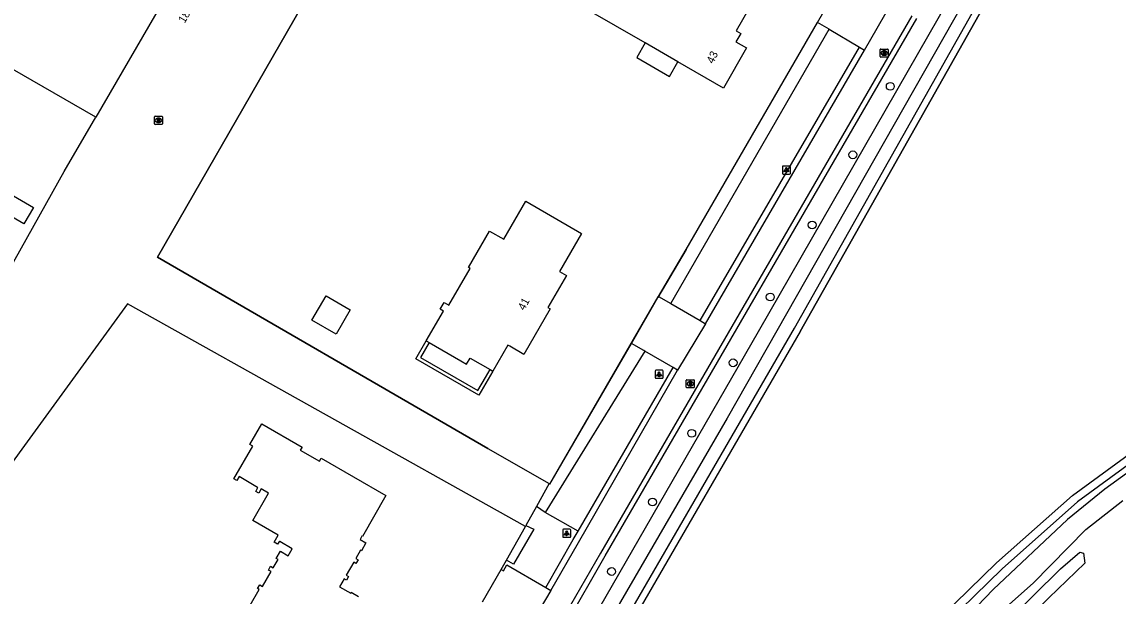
# Model space of a CAD drawing. Extents: x 156502 to 159074, y 384229 to 386094.
# Drawn here: x 157237.7 to 157374.7, y 385716.9 to 385788.7 of the extents above; entities that cross this region are included whole.
import ezdxf

# ---------------------------------------------------------------- set-up
doc = ezdxf.new("R2010")
doc.units = 0
for name, color, linetype in [('IMGEO_Boom', 7, 'Continuous'), ('IMGEO_Gemengd_bos', 7, 'Continuous'), ('IMGEO_Grasland_overig', 7, 'Continuous'), ('IMGEO_Greppel_droge_sloot', 7, 'Continuous'), ('IMGEO_Groenvoorziening', 7, 'Continuous'), ('IMGEO_Hek', 7, 'Continuous'), ('IMGEO_Lichtpunt', 7, 'Continuous'), ('IMGEO_Muur', 7, 'Continuous'), ('IMGEO_Pand', 7, 'Continuous'), ('IMGEO_Pand_nummerreeks', 7, 'Continuous'), ('IMGEO_Pand_overbouw', 7, 'Continuous'), ('IMGEO_Rijbaan_lokaal_halfverhard', 7, 'Continuous'), ('IMGEO_Rijbaan_lokaal_onverhard', 7, 'Continuous'), ('IMGEO_Rijbaan_lokaal_open', 7, 'Continuous'), ('IMGEO_Rioolput', 7, 'Continuous'), ('IMGEO_Waterloop', 7, 'Continuous')]:
    doc.layers.add(name, color=color, linetype=linetype)

msp = doc.modelspace()

# ---------------------------------------------------------------- linework, layer by layer
at = {"layer": 'IMGEO_Boom'}
for centre in [(157346.21, 385780.62), (157341.53, 385772.07), (157336.45, 385763.3), (157331.21, 385754.3), (157326.57, 385746.07), (157321.4, 385737.26), (157316.5, 385728.67), (157311.38, 385719.98)]:
    msp.add_circle(centre, 0.489, dxfattribs=at)
at = {"layer": 'IMGEO_Gemengd_bos'}
for points in [[(157395.47, 385857.33), (157372.59, 385816.74), (157334.96, 385750), (157287.88, 385668.68), (157271.39, 385640.19), (157191.03, 385500), (157152.55, 385432.88), (157150.67, 385429.59), (157146.17, 385421.74)], [(157272.04, 385820.04), (157246.93, 385776.79)], [(157272.04, 385820.04), (157275.52, 385818.05), (157285.22, 385812.46), (157254.63, 385759.26), (157295.91, 385735.36), (157303.57, 385730.97)], [(157300.61, 385725.63), (157250.89, 385753.43), (157232.44, 385728.12), (157222.97, 385734.27), (157242.96, 385769.96), (157246.93, 385776.79)], [(157303.57, 385730.97), (157301.99, 385728.11)], [(157301.99, 385728.11), (157300.68, 385725.75)], [(157300.61, 385725.63), (157300.68, 385725.75)]]:
    msp.add_lwpolyline(points, dxfattribs=at)
at = {"layer": 'IMGEO_Grasland_overig'}
msp.add_lwpolyline([(157246.93, 385776.79), (157216.71, 385794.2)], dxfattribs=at)
at = {"layer": 'IMGEO_Greppel_droge_sloot'}
for points in [[(157393.36, 385858.05), (157393.11, 385857.61), (157362.75, 385804.11), (157325.82, 385739.17), (157293.92, 385684.22), (157277.51, 385655.56), (157259.26, 385623.71), (157238.62, 385587.75), (157224.85, 385563.79), (157203.07, 385525.9), (157174.27, 385475.36), (157161.25, 385452.05), (157151.08, 385433.93), (157146.7, 385427.27), (157144.86, 385424.97)], [(157146.46, 385424.36), (157148.98, 385428.05), (157150.58, 385430.99), (157151.89, 385433.4), (157190.31, 385500.41), (157270.67, 385640.6), (157287.16, 385669.09), (157334.24, 385750.41), (157371.86, 385817.15), (157394.6, 385857.47)]]:
    msp.add_lwpolyline(points, dxfattribs=at)
at = {"layer": 'IMGEO_Groenvoorziening'}
for points in [[(157284.2, 385670.89), (157329.73, 385750), (157392.25, 385858.97)], [(157317.26, 385754.36), (157320.72, 385760.25), (157337.11, 385788.6)], [(157318.78, 385753.48), (157338.56, 385787.75)], [(157315.53, 385747.53), (157303.1, 385727.35)], [(157303.57, 385730.97), (157303.66, 385730.92), (157313.86, 385748.5)], [(157303.1, 385727.35), (157301.99, 385728.11)], [(157307.21, 385725.01), (157303.1, 385727.35)], [(157300.68, 385725.75), (157301.65, 385725.27), (157299.14, 385720.9), (157298.24, 385721.4)], [(157298.24, 385721.4), (157300.61, 385725.63)], [(157297.59, 385720.23), (157298.24, 385721.4)]]:
    msp.add_lwpolyline(points, dxfattribs=at)
at = {"layer": 'IMGEO_Hek'}
for points in [[(157334.96, 385750), (157372.59, 385816.74)], [(157295.91, 385735.36), (157254.63, 385759.26), (157285.22, 385812.46)], [(157320.72, 385760.25), (157337.11, 385788.6)], [(157320.72, 385760.25), (157317.18, 385754.23)], [(157303.57, 385730.97), (157303.66, 385730.92), (157317.21, 385754.31)], [(157334.96, 385750), (157287.88, 385668.68)], [(157295.91, 385735.36), (157303.57, 385730.97)]]:
    msp.add_lwpolyline(points, dxfattribs=at)
at = {"layer": 'IMGEO_Lichtpunt'}
for p, q in [((157332.73, 385770.56), (157332.73, 385769.75)), ((157332.73, 385770.56), (157332.73, 385769.75)), ((157333.63, 385770.65), (157332.82, 385770.65)), ((157333.63, 385770.65), (157332.82, 385770.65)), ((157332.82, 385769.66), (157333.63, 385769.66)), ((157332.82, 385769.66), (157333.63, 385769.66)), ((157333.73, 385769.75), (157333.73, 385770.56)), ((157333.73, 385769.75), (157333.73, 385770.56)), ((157316.82, 385745.04), (157316.82, 385744.23)), ((157316.82, 385745.04), (157316.82, 385744.23)), ((157317.73, 385745.13), (157316.92, 385745.13)), ((157317.73, 385745.13), (157316.92, 385745.13)), ((157317.82, 385744.23), (157317.82, 385745.04)), ((157317.82, 385744.23), (157317.82, 385745.04)), ((157316.92, 385744.14), (157317.73, 385744.14)), ((157316.92, 385744.14), (157317.73, 385744.14)), ((157305.28, 385725.17), (157305.28, 385724.36)), ((157305.28, 385725.17), (157305.28, 385724.36)), ((157306.18, 385725.27), (157305.37, 385725.27)), ((157306.18, 385725.27), (157305.37, 385725.27)), ((157305.37, 385724.27), (157306.18, 385724.27)), ((157305.37, 385724.27), (157306.18, 385724.27)), ((157306.27, 385724.36), (157306.27, 385725.17)), ((157306.27, 385724.36), (157306.27, 385725.17))]:
    msp.add_line(p, q, dxfattribs=at)
for points in [[(157333.1, 385770.22), (157333.14, 385770.19), (157332.95, 385769.93), (157332.92, 385769.96), (157333.1, 385770.22)], [(157333.2, 385770.17), (157333.25, 385770.17), (157333.25, 385769.85), (157333.2, 385769.85), (157333.2, 385770.17)], [(157333.31, 385770.19), (157333.35, 385770.22), (157333.54, 385769.96), (157333.5, 385769.93), (157333.31, 385770.19)], [(157317.2, 385744.7), (157317.24, 385744.68), (157317.05, 385744.41), (157317.01, 385744.44), (157317.2, 385744.7)], [(157317.3, 385744.66), (157317.35, 385744.66), (157317.35, 385744.33), (157317.3, 385744.33), (157317.3, 385744.66)], [(157317.41, 385744.68), (157317.45, 385744.7), (157317.63, 385744.44), (157317.6, 385744.41), (157317.41, 385744.68)], [(157305.65, 385724.83), (157305.69, 385724.81), (157305.5, 385724.54), (157305.46, 385724.57), (157305.65, 385724.83)], [(157305.75, 385724.79), (157305.8, 385724.79), (157305.8, 385724.46), (157305.75, 385724.46), (157305.75, 385724.79)], [(157305.86, 385724.81), (157305.9, 385724.83), (157306.09, 385724.57), (157306.05, 385724.54), (157305.86, 385724.81)]]:
    msp.add_lwpolyline(points, dxfattribs=at)
for centre in [(157333.23, 385770.36), (157317.32, 385744.84), (157305.78, 385724.97)]:
    msp.add_circle(centre, 0.0994, dxfattribs=at)
for centre, start, end in [((157332.82, 385770.56), 90, 180), ((157332.82, 385770.56), 90, 180), ((157332.82, 385769.75), 180, 270), ((157332.82, 385769.75), 180, 270), ((157333.63, 385770.56), 0, 90), ((157333.63, 385770.56), 0, 90), ((157333.63, 385769.75), 270, 0), ((157333.63, 385769.75), 270, 360), ((157316.92, 385745.04), 90, 180), ((157316.92, 385745.04), 90, 180), ((157317.73, 385745.04), 0, 90), ((157317.73, 385745.04), 0, 90), ((157316.92, 385744.23), 180, 270), ((157316.92, 385744.23), 180, 270), ((157317.73, 385744.23), 270, 0), ((157317.73, 385744.23), 270, 360), ((157305.37, 385725.17), 90, 180), ((157305.37, 385725.17), 90, 180), ((157305.37, 385724.36), 180, 270), ((157305.37, 385724.36), 180, 270), ((157306.18, 385725.17), 0, 90), ((157306.18, 385725.17), 0, 90), ((157306.18, 385724.36), 270, 0), ((157306.18, 385724.36), 270, 360)]:
    msp.add_arc(centre, 0.0946, start, end, dxfattribs=at)
at = {"layer": 'IMGEO_Muur'}
for points in [[(157296.54, 385745.04), (157295.96, 385744.03), (157294.81, 385742.04), (157286.93, 385746.58), (157288.22, 385748.82)], [(157288.58, 385748.61), (157287.5, 385746.73), (157294.67, 385742.59), (157295.61, 385744.23), (157296.19, 385745.24)]]:
    msp.add_lwpolyline(points, dxfattribs=at)
at = {"layer": 'IMGEO_Pand'}
for points in [[(157317.55, 385799.56), (157316.78, 385798.21), (157320.72, 385795.94), (157320.43, 385795.41), (157328.72, 385790.61), (157326.97, 385787.58), (157327.53, 385787.24), (157326.92, 385786.2), (157328.26, 385785.43), (157325.36, 385780.38), (157319.65, 385783.69), (157315.58, 385786.05), (157304.76, 385792.32), (157311.15, 385803.25), (157317.55, 385799.56)], [(157231.7, 385767.06), (157232.9, 385769.12), (157239.12, 385765.48), (157237.93, 385763.43), (157231.7, 385767.06)], [(157288.22, 385748.82), (157290.36, 385752.54), (157289.98, 385752.76), (157290.47, 385753.61), (157291.05, 385753.28), (157293.69, 385757.86), (157293.49, 385757.98), (157296.12, 385762.54), (157297.92, 385761.51), (157300.66, 385766.27), (157307.61, 385762.25), (157304.88, 385757.48), (157305.73, 385756.99), (157303.43, 385752.99), (157303.72, 385752.82), (157300.42, 385747.11), (157298.66, 385748.13), (157298.42, 385748.26), (157296.54, 385745.04)], [(157278.72, 385752.69), (157276.97, 385749.66), (157273.94, 385751.42), (157275.7, 385754.45), (157278.72, 385752.69)], [(157288.22, 385748.82), (157288.58, 385748.61)], [(157288.58, 385748.61), (157292.55, 385746.32), (157293.25, 385745.91), (157293.7, 385746.67), (157296.19, 385745.24)], [(157296.19, 385745.24), (157296.54, 385745.04)], [(157264.84, 385731.84), (157264.55, 385731.34), (157264.18, 385731.56), (157266.55, 385735.65), (157266.17, 385735.87), (157267.66, 385738.45), (157272.7, 385735.53), (157272.48, 385735.15), (157274.88, 385733.78), (157275.1, 385734.16), (157283.19, 385729.49), (157280.26, 385724.37), (157280.18, 385724.41), (157279.95, 385724), (157280.68, 385723.58), (157280.11, 385722.58), (157280.01, 385722.64), (157279.42, 385721.62), (157279.71, 385721.45), (157279.44, 385720.99), (157279.16, 385721.15), (157278.23, 385719.52), (157278.5, 385719.36), (157278.24, 385718.89), (157277.95, 385719.06), (157277.39, 385718.09), (157278.79, 385717.29), (157278.85, 385717.39), (157279.75, 385716.87)], [(157266.2, 385715.79), (157267.33, 385717.75), (157267.15, 385717.85), (157267.42, 385718.31), (157267.76, 385718.12), (157268.83, 385719.98), (157268.49, 385720.17), (157268.75, 385720.64), (157269.09, 385720.44), (157269.7, 385721.5), (157269.48, 385721.62), (157270, 385722.51), (157270.96, 385721.95), (157271.48, 385722.84), (157269.92, 385723.74), (157269.87, 385723.77), (157269.65, 385723.39), (157269.2, 385723.65), (157269.71, 385724.54), (157266.53, 385726.38), (157268.5, 385729.78), (157267.59, 385730.3), (157267.28, 385729.77), (157266.91, 385729.99), (157267.19, 385730.47), (157267.15, 385730.49), (157264.84, 385731.84)]]:
    msp.add_lwpolyline(points, dxfattribs=at)
at = {"layer": 'IMGEO_Pand_overbouw'}
msp.add_lwpolyline([(157315.58, 385786.05), (157314.52, 385784.22), (157318.6, 385781.86), (157319.65, 385783.69)], close=True, dxfattribs=at)
at = {"layer": 'IMGEO_Rijbaan_lokaal_halfverhard'}
for points in [[(157281.97, 385672.23), (157287.9, 385682.57), (157297.81, 385699.74), (157305.61, 385713.27), (157310.6, 385721.93), (157349.52, 385789.09)], [(157322.45, 385751.34), (157342.35, 385785.53)], [(157307.21, 385725.01), (157319.08, 385745.47)], [(157303.16, 385717.99), (157306.6, 385723.98), (157307.21, 385725.01)]]:
    msp.add_lwpolyline(points, dxfattribs=at)
at = {"layer": 'IMGEO_Rijbaan_lokaal_onverhard'}
for points in [[(157452.62, 385772.03), (157439.68, 385768.72), (157433.84, 385766.77), (157420.89, 385761.55), (157420.02, 385761.13), (157410.79, 385755.97), (157406.16, 385753.14), (157401.41, 385750), (157388.24, 385741.27), (157373.02, 385730.27), (157368.37, 385726.47), (157359.05, 385717.74), (157350, 385708.26), (157335.38, 385692.58), (157330.69, 385686.32), (157328.32, 385682.73), (157324.09, 385675.08), (157315.99, 385658.02), (157313.72, 385652.7), (157308.77, 385638.36), (157307.36, 385633.66)], [(157309.76, 385633.05), (157311.39, 385637.62), (157313.24, 385643.86), (157315.24, 385649.68), (157317.27, 385655), (157321.88, 385665.22), (157323.45, 385668.06), (157328.02, 385675.4), (157330.34, 385679.68), (157332.67, 385684.44), (157335.57, 385689), (157338.44, 385692.86), (157340.46, 385695.22), (157355.14, 385709.74), (157361.1, 385715.9), (157364.06, 385718.55), (157370.65, 385725.25), (157375.26, 385728.85)]]:
    msp.add_lwpolyline(points, dxfattribs=at)
at = {"layer": 'IMGEO_Rijbaan_lokaal_open'}
for points in [[(157337.11, 385788.6), (157340.4, 385794.34)], [(157342.98, 385785.16), (157346.33, 385790.92)], [(157348.91, 385789.44), (157309.98, 385722.29), (157304.98, 385713.63), (157297.19, 385700.1), (157287.28, 385682.93), (157276.98, 385664.99), (157272.99, 385658.15), (157259.7, 385634.92)], [(157338.56, 385787.75), (157337.11, 385788.6)], [(157338.56, 385787.75), (157342.35, 385785.53)], [(157323.12, 385750.95), (157342.98, 385785.16)], [(157342.35, 385785.53), (157342.98, 385785.16)], [(157313.86, 385748.5), (157317.18, 385754.23), (157317.26, 385754.36)], [(157317.26, 385754.36), (157318.78, 385753.48)], [(157318.78, 385753.48), (157322.45, 385751.34)], [(157323.12, 385750.95), (157319.61, 385745.16)], [(157322.45, 385751.34), (157323.12, 385750.95)], [(157315.53, 385747.53), (157315.4, 385747.6), (157313.86, 385748.5)], [(157319.08, 385745.47), (157315.53, 385747.53)], [(157303.78, 385717.63), (157307.23, 385723.61), (157319.61, 385745.16)], [(157319.61, 385745.16), (157319.08, 385745.47)], [(157295.26, 385716.2), (157297.59, 385720.23)], [(157297.59, 385720.23), (157297.87, 385720.06), (157298.3, 385720.81), (157303.16, 385717.99)], [(157303.78, 385717.63), (157302.35, 385715.15), (157300.61, 385712.13)], [(157303.16, 385717.99), (157303.78, 385717.63)]]:
    msp.add_lwpolyline(points, dxfattribs=at)
at = {"layer": 'IMGEO_Rioolput'}
for p, q in [((157344.95, 385784.35), (157344.95, 385785.21)), ((157345.02, 385785.28), (157345.87, 385785.28)), ((157345.43, 385785.06), (157345.46, 385785.06)), ((157345.46, 385784.5), (157345.43, 385784.5)), ((157345.95, 385785.21), (157345.95, 385784.35)), ((157345.87, 385784.28), (157345.02, 385784.28)), ((157254.25, 385775.95), (157254.25, 385776.8)), ((157254.33, 385776.88), (157255.18, 385776.88)), ((157254.74, 385776.65), (157254.77, 385776.65)), ((157255.26, 385776.8), (157255.26, 385775.95)), ((157255.18, 385775.87), (157254.33, 385775.87)), ((157254.76, 385776.1), (157254.74, 385776.1)), ((157320.72, 385743.02), (157320.72, 385743.88)), ((157320.79, 385743.95), (157321.65, 385743.95)), ((157321.21, 385743.73), (157321.23, 385743.73)), ((157321.72, 385743.88), (157321.72, 385743.02)), ((157321.65, 385742.95), (157320.79, 385742.95)), ((157321.23, 385743.17), (157321.2, 385743.17))]:
    msp.add_line(p, q, dxfattribs=at)
for points in [[(157344.95, 385784.35), (157344.95, 385785.21)], [(157345.02, 385785.28), (157345.87, 385785.28)], [(157345.53, 385784.98), (157345.28, 385784.98), (157345.28, 385784.58)], [(157345.28, 385784.58), (157345.41, 385784.58), (157345.41, 385784.74), (157345.42, 385784.74)], [(157345.46, 385784.9), (157345.41, 385784.9), (157345.41, 385784.82)], [(157345.41, 385784.82), (157345.46, 385784.82)], [(157345.46, 385784.71), (157345.54, 385784.58), (157345.67, 385784.58), (157345.61, 385784.71)], [(157345.95, 385785.21), (157345.95, 385784.35)], [(157345.87, 385784.28), (157345.02, 385784.28)], [(157254.25, 385775.95), (157254.25, 385776.8)], [(157254.33, 385776.88), (157255.18, 385776.88)], [(157254.84, 385776.57), (157254.59, 385776.57), (157254.59, 385776.17)], [(157254.59, 385776.17), (157254.72, 385776.17), (157254.72, 385776.34), (157254.73, 385776.34)], [(157254.77, 385776.49), (157254.72, 385776.49), (157254.72, 385776.41)], [(157254.72, 385776.41), (157254.77, 385776.41)], [(157254.77, 385776.31), (157254.84, 385776.17), (157254.98, 385776.17), (157254.92, 385776.3)], [(157255.26, 385776.8), (157255.26, 385775.95)], [(157255.18, 385775.87), (157254.33, 385775.87)], [(157320.72, 385743.02), (157320.72, 385743.88)], [(157320.79, 385743.95), (157321.65, 385743.95)], [(157321.31, 385743.65), (157321.06, 385743.65), (157321.06, 385743.25)], [(157321.06, 385743.25), (157321.18, 385743.25), (157321.18, 385743.41), (157321.19, 385743.41)], [(157321.23, 385743.57), (157321.18, 385743.57), (157321.18, 385743.49)], [(157321.18, 385743.49), (157321.23, 385743.49)], [(157321.24, 385743.38), (157321.31, 385743.25), (157321.45, 385743.25), (157321.38, 385743.38)], [(157321.72, 385743.88), (157321.72, 385743.02)], [(157321.65, 385742.95), (157320.79, 385742.95)]]:
    msp.add_lwpolyline(points, dxfattribs=at)
for centre, radius, start, end in [((157345.02, 385785.2), 0.0765, 91.552, 178.448), ((157345.02, 385785.2), 0.0765, 91.552, 178.448), ((157345.42, 385784.69), 0.0533, 26.0293, 88.6989), ((157345.47, 385784.8), 0.0964, 77.0061, 93.1865), ((157345.44, 385785.01), 0.19, 274.7715, 282.9687), ((157345.48, 385784.86), 0.0378, 276.6634, 79.6772), ((157345.53, 385784.87), 0.109, 350.3612, 89.416), ((157345.53, 385784.87), 0.112, 277.5842, 350.9817), ((157345.52, 385784.65), 0.108, 29.5134, 73.7905), ((157345.87, 385785.2), 0.0765, 1.552, 88.448), ((157345.87, 385785.2), 0.0765, 1.552, 88.448), ((157345.02, 385784.35), 0.0765, 181.552, 268.448), ((157345.02, 385784.35), 0.0765, 181.552, 268.448), ((157345.87, 385784.35), 0.0765, 271.552, 358.448), ((157345.87, 385784.35), 0.0765, 271.552, 358.448), ((157254.33, 385776.8), 0.0765, 91.552, 178.448), ((157254.33, 385776.8), 0.0765, 91.552, 178.448), ((157254.72, 385776.28), 0.0533, 26.0293, 88.6989), ((157254.77, 385776.4), 0.0964, 77.0061, 93.1865), ((157254.75, 385776.6), 0.19, 274.7715, 282.9687), ((157254.79, 385776.45), 0.0378, 276.6634, 79.6772), ((157254.84, 385776.46), 0.109, 350.3612, 89.416), ((157254.84, 385776.46), 0.112, 277.5842, 350.9817), ((157254.82, 385776.25), 0.108, 29.5134, 73.7905), ((157255.18, 385776.8), 0.0765, 1.552, 88.448), ((157255.18, 385776.8), 0.0765, 1.552, 88.448), ((157254.33, 385775.95), 0.0765, 181.552, 268.448), ((157254.33, 385775.95), 0.0765, 181.552, 268.448), ((157255.18, 385775.95), 0.0765, 271.552, 358.448), ((157255.18, 385775.95), 0.0765, 271.552, 358.448), ((157320.8, 385743.87), 0.0765, 91.552, 178.448), ((157320.8, 385743.87), 0.0765, 91.552, 178.448), ((157321.19, 385743.36), 0.0533, 26.0293, 88.6989), ((157321.24, 385743.47), 0.0964, 77.0061, 93.1865), ((157321.22, 385743.68), 0.19, 274.7715, 282.9687), ((157321.25, 385743.53), 0.0378, 276.6634, 79.6772), ((157321.31, 385743.54), 0.109, 350.3612, 89.416), ((157321.31, 385743.54), 0.112, 277.5842, 350.9817), ((157321.29, 385743.32), 0.108, 29.5134, 73.7905), ((157321.64, 385743.87), 0.0765, 1.552, 88.448), ((157321.64, 385743.87), 0.0765, 1.552, 88.448), ((157320.8, 385743.03), 0.0765, 181.552, 268.448), ((157320.8, 385743.03), 0.0765, 181.552, 268.448), ((157321.64, 385743.03), 0.0765, 271.552, 358.448), ((157321.64, 385743.03), 0.0765, 271.552, 358.448)]:
    msp.add_arc(centre, radius, start, end, dxfattribs=at)
for centre, major_axis, ratio, start_param, end_param in [((157345.43, 385784.78), (-0.387, 0.002), 0.722429, 4.712389, 7.853982), ((157345.46, 385784.78), (-0.39, 0.002), 0.717154, 1.570796, 4.712389), ((157254.74, 385776.37), (-0.387, 0.002), 0.722429, 4.712389, 7.853982), ((157254.77, 385776.37), (-0.39, 0.002), 0.717154, 1.570796, 4.712389), ((157321.21, 385743.45), (-0.387, 0.002), 0.722429, 4.712389, 7.853982), ((157321.23, 385743.45), (-0.39, 0.002), 0.717154, 1.570796, 4.712389)]:
    msp.add_ellipse(centre, major_axis=major_axis, ratio=ratio, start_param=start_param, end_param=end_param, dxfattribs=at)
at = {"layer": 'IMGEO_Waterloop'}
for points in [[(157313.88, 385657.2), (157319.42, 385669.46), (157326.38, 385682.33), (157329.75, 385687.46), (157336.36, 385696.35), (157342.79, 385703.77), (157350.84, 385712.61), (157359.49, 385721.05), (157368.98, 385729.49), (157384.16, 385740.55), (157398.32, 385750), (157403.23, 385753.28), (157414.47, 385760.23), (157425.48, 385766.09), (157436.74, 385770.62), (157451.12, 385774.84), (157465.72, 385778.54), (157474.31, 385780.52)], [(157474.54, 385779.54), (157465.96, 385777.56), (157451.38, 385773.86), (157437.07, 385769.66), (157425.91, 385765.18), (157414.97, 385759.35), (157403.77, 385752.43), (157400.13, 385750), (157384.74, 385739.73), (157369.61, 385728.71), (157360.18, 385720.32), (157351.57, 385711.91), (157343.55, 385703.1), (157337.15, 385695.72), (157330.58, 385686.89), (157327.25, 385681.81), (157320.32, 385669.01), (157314.81, 385656.81), (157309.55, 385643.22), (157304.76, 385626.85), (157289.94, 385563.14), (157287.02, 385552.69)], [(157320.16, 385654.3), (157326.49, 385667.85), (157329.13, 385673.02), (157336.2, 385684.73), (157342.72, 385693.77), (157347.46, 385699.15), (157354.54, 385706.7), (157360.71, 385713.62), (157367.5, 385720.32), (157369.9, 385722.39), (157370.36, 385722.27), (157370.53, 385721.03), (157366.02, 385716.7), (157358.94, 385709.5), (157353.97, 385704.1), (157342.4, 385690.74)]]:
    msp.add_lwpolyline(points, dxfattribs=at)

# ---------------------------------------------------------------- texts
at = {"layer": 'IMGEO_Pand_nummerreeks'}
for s, rotation, p in [('18/N02', 60.1601, (157258.03, 385788.44)), ('43', 64.0624, (157324.08, 385783.38)), ('41', 61.6955, (157300.48, 385752.54))]:
    msp.add_text(s, height=1, rotation=rotation, dxfattribs=at).set_placement(p)

doc.saveas('drawing.dxf')
